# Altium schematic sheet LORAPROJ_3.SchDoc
size A3; SheetNumber: 3; SheetTotal: 3
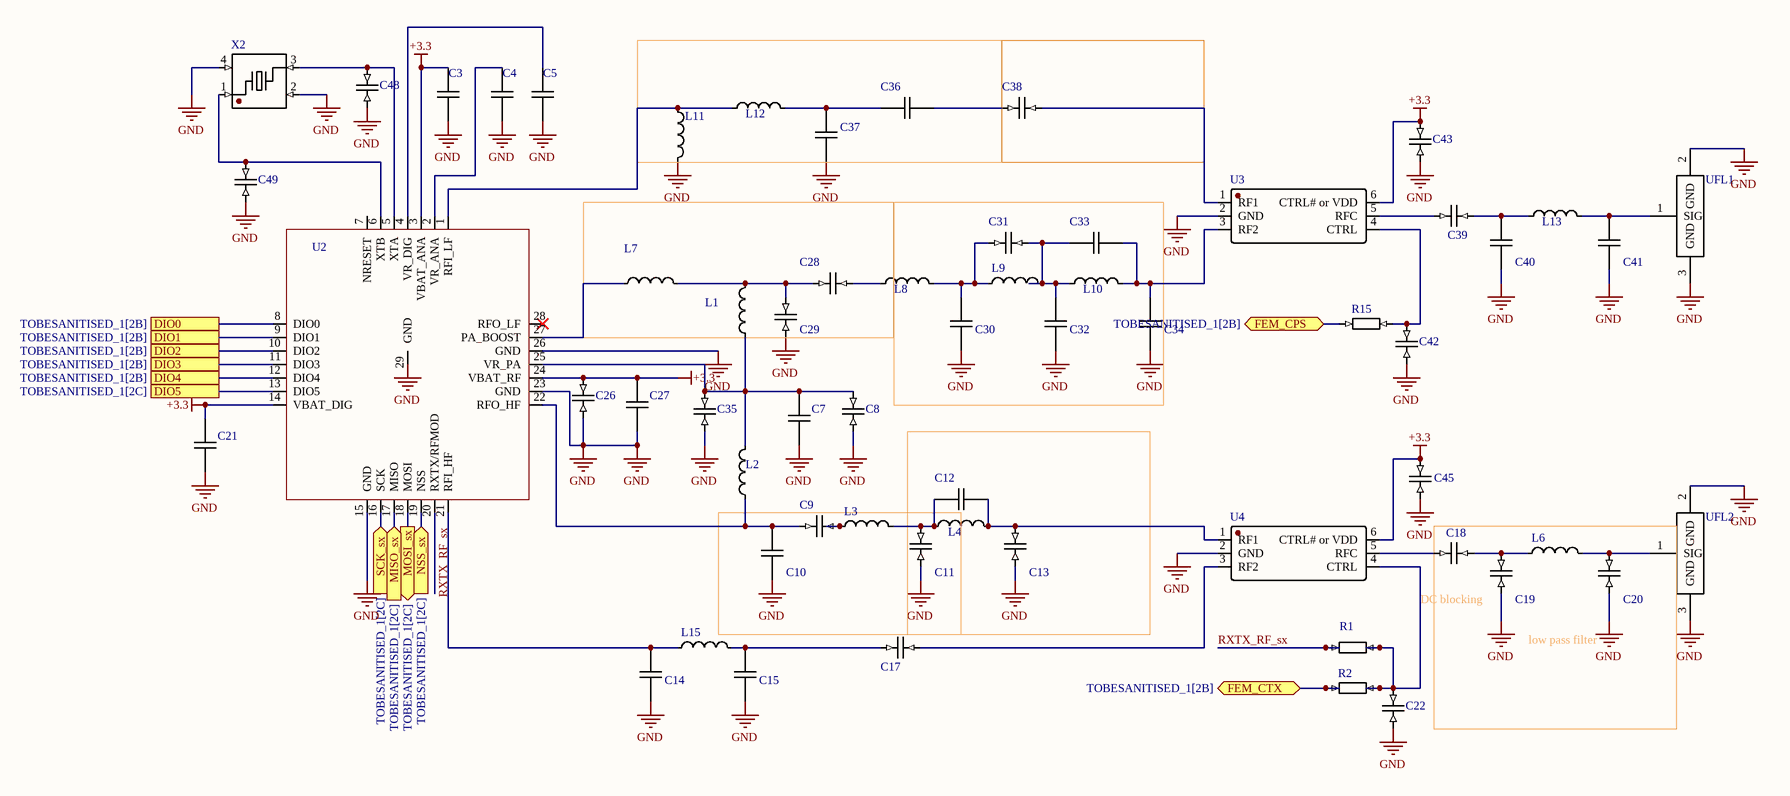
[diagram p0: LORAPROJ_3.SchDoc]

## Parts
C3  (no value)  [CAP_0603]
C4  (no value)  [CAP_0603]
C5  (no value)  [CAP_0603]
C7  (no value)  [CAP_0603]
C8  (no value)  [CAP_0603]
C9  (no value)  [CAP_0603]
C10  (no value)  [CAP_0603]
C11  (no value)  [CAP_0603]
C12  (no value)  [CAP_0603]
C13  (no value)  [CAP_0603]
C14  (no value)  [CAP_0603]
C15  (no value)  [CAP_0603]
C17  (no value)  [CAP_0603]
C18  (no value)  [CAP_0603]
C19  (no value)  [CAP_0603]
C20  (no value)  [CAP_0603]
C21  (no value)  [CAP_0603]
C22  (no value)  [CAP_0603]
C26  (no value)  [CAP_0603]
C27  (no value)  [CAP_0603]
C28  (no value)  [CAP_0603]
C29  (no value)  [CAP_0603]
C30  (no value)  [CAP_0603]
C31  (no value)  [CAP_0603]
C32  (no value)  [CAP_0603]
C33  (no value)  [CAP_0603]
C34  (no value)  [CAP_0603]
C35  (no value)  [CAP_0603]
C36  (no value)  [CAP_0603]
C37  (no value)  [CAP_0603]
C38  (no value)  [CAP_0603]
C39  (no value)  [CAP_0603]
C40  (no value)  [CAP_0603]
C41  (no value)  [CAP_0603]
C42  (no value)  [CAP_0603]
C43  (no value)  [CAP_0603]
C45  (no value)  [CAP_0603]
C48  (no value)  [CAP_0603]
C49  (no value)  [CAP_0603]
L1  (no value)  [IND_0603]
L2  (no value)  [IND_0603]
L3  (no value)  [IND_0603]
L4  (no value)  [IND_0603]
L6  (no value)  [IND_0603]
L7  (no value)  [IND_0603]
L8  (no value)  [IND_0603]
L9  (no value)  [IND_0603]
L10  (no value)  [IND_0603]
L11  (no value)  [IND_0603]
L12  (no value)  [IND_0603]
L13  (no value)  [IND_0603]
L15  (no value)  [IND_0603]
R1  (no value)  [RES_0603]
R2  (no value)  [RES_0603]
R15  (no value)  [RES_0603]
U2  (no value)  [QFN-28_6x6_P0.65_EP]
U3  (no value)  [SC-70-6]
U4  (no value)  [SC-70-6]
UFL1  (no value)  [RF_COAX_SMD]
UFL2  (no value)  [RF_COAX_SMD]
X2  (no value)  [XTAL_SMD_2016_4P]

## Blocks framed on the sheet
low pass filter: C18-C20 L6

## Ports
DIO0 (see TOBESANITISED_1[2B]), DIO1 (see TOBESANITISED_1[2B]), DIO2 (see TOBESANITISED_1[2B]), DIO3 (see TOBESANITISED_1[2B]), DIO4 (see TOBESANITISED_1[2B]), DIO5 (see TOBESANITISED_1[2C]), FEM_CPS (bidir, see TOBESANITISED_1[2B]), FEM_CTX (bidir, see TOBESANITISED_1[2B]), MISO_sx (in, see TOBESANITISED_1[2C]), MOSI_sx (out, see TOBESANITISED_1[2C]), NSS_sx (in, see TOBESANITISED_1[2C]), SCK_sx (in, see TOBESANITISED_1[2C])

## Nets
+3.3: C3.1 C21.2 C26.2 C27.2 C43.2 C45.2 U2.3(VBAT_ANA) U2.14(VBAT_DIG) U2.24(VBAT_RF) U3.6(CTRL#_or_VDD) U4.6(CTRL#_or_VDD)
GND: C3.2 C4.2 C5.2 C7.1 C8.1 C10.1 C11.1 C13.1 C14.1 C15.1 C19.1 C20.1 C21.1 C22.1 C26.1 C27.1 C29.1 C30.2 C32.1 C34.2 C35.1 C37.2 C40.2 C41.2 C42.1 C43.1 C45.1 C48.1 C49.1 L11.2 U2.15(GND) U2.23(GND) U2.26(GND) U2.29(GND) U3.2(GND) U4.2(GND) UFL1.2(GND) UFL1.3(GND) UFL2.2(GND) UFL2.3(GND) X2.2(GND) X2.4(GND)
DIO0: U2.8(DIO0) ; port DIO0
DIO1: U2.9(DIO1) ; port DIO1
DIO2: U2.10(DIO2) ; port DIO2
DIO3: U2.11(DIO3) ; port DIO3
DIO4: U2.12(DIO4) ; port DIO4
DIO5: U2.13(DIO5) ; port DIO5
FEM_CPS: R15.1 ; port FEM_CPS
FEM_CTX: R2.1 ; port FEM_CTX
MISO_sx: U2.17(MISO) ; port MISO_sx
MOSI_sx: U2.18(MOSI) ; port MOSI_sx
NSS_sx: U2.19(NSS) ; port NSS_sx
RXTX_RF_sx: R1.2 U2.20(RXTX/RFMOD)
SCK_sx: U2.16(SCK) ; port SCK_sx
NetC4_1: C4.1 U2.2(VR_ANA)
NetC5_1: C5.1 U2.4(VR_DIG)
NetC7_2: C7.2 C8.2 C35.2 L1.1 L2.1 U2.25(VR_PA)
NetC9_1: C9.1 C10.2 L2.2 U2.22(RFO_HF)
NetC9_2: C9.2 L3.1
NetC11_2: C11.2 C12.1 L3.2 L4.1
NetC12_2: C12.2 C13.2 L4.2 U4.1(RF1)
NetC14_2: C14.2 L15.1 U2.21(RFI_HF)
NetC15_2: C15.2 C17.2 L15.2
NetC17_1: C17.1 U4.3(RF2)
NetC18_1: C18.1 U4.5(RFC)
NetC18_2: C18.2 C19.2 L6.1
NetC20_2: C20.2 L6.2 UFL2.1(SIG)
NetC22_2: C22.2 R1.1 R2.2 U4.4(CTRL)
NetC28_1: C28.1 C29.2 L1.2 L7.2
NetC28_2: C28.2 L8.2
NetC30_1: C30.1 C31.1 L8.1 L9.1
NetC31_2: C31.2 C32.2 C33.2 L9.2 L10.2
NetC33_1: C33.1 C34.1 L10.1 U3.3(RF2)
NetC36_1: C36.1 C37.1 L12.1
NetC36_2: C36.2 C38.1
NetC38_2: C38.2 U3.1(RF1)
NetC39_1: C39.1 U3.5(RFC)
NetC39_2: C39.2 C40.1 L13.2
NetC41_1: C41.1 L13.1 UFL1.1(SIG)
NetC42_2: C42.2 R15.2 U3.4(CTRL)
NetC48_2: C48.2 U2.5(XTA) X2.3
NetC49_2: C49.2 U2.6(XTB) X2.1
NetL7_1: L7.1 U2.27(PA_BOOST)
NetL11_1: L11.1 L12.2 U2.1(RFI_LF)

Not connected (* = marked no-connect by the designer): U2 7(NRESET) 28(RFO_LF)*

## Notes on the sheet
- (near C19) DC blocking

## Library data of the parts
C3-C5 C7-C15 C17-C22 C26-C43 C45 C48 C49 = CAP
L1-L4 L6-L13 L15 = IND
R1 R2 R15 = RES
U2 = IC_U2
U3 = IC_U3
U4 = IC_U4
UFL1 UFL2 = CONN_RF
X2 = XTAL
